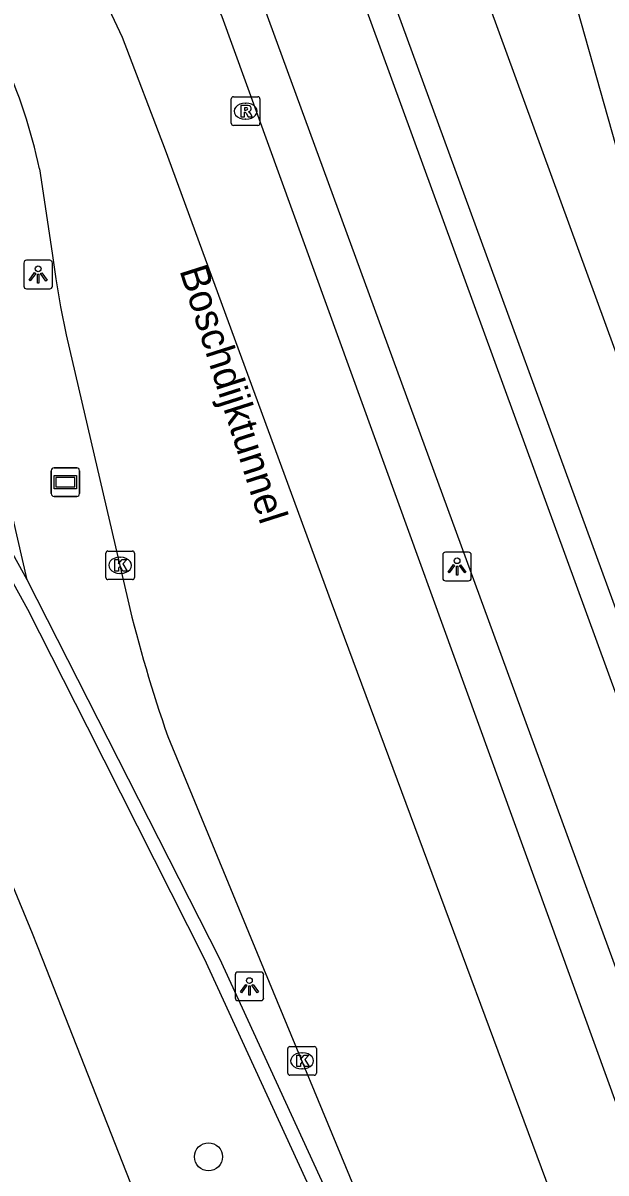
# Model space of a CAD drawing. Extents: x 160806 to 161707, y 383697 to 384148.
# Drawn here: x 161073.56 to 161093.93, y 383742.52 to 383782.67 of the extents above; entities that cross this region are included whole.
import ezdxf

# ---------------------------------------------------------------- set-up
doc = ezdxf.new("R2010")
doc.units = 0
for name, color, linetype in [('IMGEO_Boom', 7, 'Continuous'), ('IMGEO_Fietspad_open', 7, 'Continuous'), ('IMGEO_Kolk', 7, 'Continuous'), ('IMGEO_Lichtpunt', 7, 'Continuous'), ('IMGEO_Muur', 7, 'Continuous'), ('IMGEO_Openbare_ruimte_label', 7, 'Continuous'), ('IMGEO_OVBaan_gesloten', 7, 'Continuous'), ('IMGEO_Reclamebord', 7, 'Continuous'), ('IMGEO_Rijbaan_lokaal_gesloten', 7, 'Continuous'), ('IMGEO_Rioolput', 7, 'Continuous'), ('IMGEO_Voetpad_open', 7, 'Continuous')]:
    doc.layers.add(name, color=color, linetype=linetype)

msp = doc.modelspace()

# ---------------------------------------------------------------- linework, layer by layer
at = {"layer": 'IMGEO_Boom'}
msp.add_circle((161080.04, 383743.082), 0.489, dxfattribs=at)
at = {"layer": 'IMGEO_Fietspad_open'}
msp.add_lwpolyline([(161080.705, 383733.661), (161080.57, 383734.119), (161077.712, 383741.17), (161074.242, 383750), (161073.898, 383750.874), (161072.088, 383755.217), (161071.934, 383755.585)], dxfattribs=at)
at = {"layer": 'IMGEO_Kolk'}
for p, q in [((161076.453, 383763.307), (161076.453, 383764.159)), ((161076.528, 383764.233), (161077.38, 383764.233)), ((161076.941, 383764.013), (161076.966, 383764.013)), ((161077.454, 383764.159), (161077.454, 383763.307)), ((161077.38, 383763.233), (161076.528, 383763.233)), ((161076.964, 383763.453), (161076.939, 383763.453)), ((161082.809, 383746.006), (161082.809, 383746.858)), ((161082.884, 383746.932), (161083.736, 383746.932)), ((161083.297, 383746.712), (161083.322, 383746.712)), ((161083.81, 383746.858), (161083.81, 383746.006)), ((161083.736, 383745.932), (161082.884, 383745.932)), ((161083.32, 383746.152), (161083.295, 383746.152))]:
    msp.add_line(p, q, dxfattribs=at)
for points in [[(161076.453, 383763.307), (161076.453, 383764.159)], [(161076.528, 383764.233), (161077.38, 383764.233)], [(161076.774, 383763.933), (161076.897, 383763.933), (161076.897, 383763.782), (161077.027, 383763.933), (161077.191, 383763.933), (161077.045, 383763.782), (161077.198, 383763.533), (161077.046, 383763.533), (161076.961, 383763.697), (161076.897, 383763.63), (161076.897, 383763.533), (161076.774, 383763.533), (161076.774, 383763.933)], [(161077.454, 383764.159), (161077.454, 383763.307)], [(161077.38, 383763.233), (161076.528, 383763.233)], [(161082.809, 383746.006), (161082.809, 383746.858)], [(161082.884, 383746.932), (161083.736, 383746.932)], [(161083.81, 383746.858), (161083.81, 383746.006)], [(161083.13, 383746.632), (161083.253, 383746.632), (161083.253, 383746.481), (161083.383, 383746.632), (161083.547, 383746.632), (161083.401, 383746.481), (161083.554, 383746.232), (161083.402, 383746.232), (161083.317, 383746.396), (161083.253, 383746.329), (161083.253, 383746.232), (161083.13, 383746.232), (161083.13, 383746.632)], [(161083.736, 383745.932), (161082.884, 383745.932)]]:
    msp.add_lwpolyline(points, dxfattribs=at)
for centre, start, end in [((161076.53, 383764.157), 91.552, 178.448), ((161076.53, 383764.157), 91.552, 178.448), ((161077.378, 383764.157), 1.552, 88.448), ((161077.378, 383764.157), 1.552, 88.448), ((161076.53, 383763.309), 181.552, 268.448), ((161076.53, 383763.309), 181.552, 268.448), ((161077.378, 383763.309), 271.552, 358.448), ((161077.378, 383763.309), 271.552, 358.448), ((161082.886, 383746.856), 91.552, 178.448), ((161082.886, 383746.856), 91.552, 178.448), ((161083.734, 383746.856), 1.552, 88.448), ((161083.734, 383746.856), 1.552, 88.448), ((161082.886, 383746.008), 181.552, 268.448), ((161082.886, 383746.008), 181.552, 268.448), ((161083.734, 383746.008), 271.552, 358.448), ((161083.734, 383746.008), 271.552, 358.448)]:
    msp.add_arc(centre, 0.0765, start, end, dxfattribs=at)
for centre, major_axis, ratio, start_param, end_param in [((161076.94, 383763.733), (-0.387, 0.002), 0.722429, 4.712389, 7.853982), ((161076.965, 383763.733), (-0.39, 0.002), 0.717154, 1.570796, 4.712389), ((161083.296, 383746.432), (-0.387, 0.002), 0.722429, 4.712389, 7.853982), ((161083.321, 383746.432), (-0.39, 0.002), 0.717154, 1.570796, 4.712389)]:
    msp.add_ellipse(centre, major_axis=major_axis, ratio=ratio, start_param=start_param, end_param=end_param, dxfattribs=at)
at = {"layer": 'IMGEO_Lichtpunt'}
for p, q in [((161074.493, 383774.382), (161073.685, 383774.382)), ((161074.493, 383774.382), (161073.685, 383774.382)), ((161073.591, 383774.287), (161073.591, 383773.48)), ((161073.591, 383774.287), (161073.591, 383773.48)), ((161074.587, 383773.48), (161074.587, 383774.287)), ((161074.587, 383773.48), (161074.587, 383774.287)), ((161073.685, 383773.386), (161074.493, 383773.386)), ((161073.685, 383773.386), (161074.493, 383773.386)), ((161088.224, 383764.093), (161088.224, 383763.286)), ((161088.224, 383764.093), (161088.224, 383763.286)), ((161089.126, 383764.188), (161088.318, 383764.188)), ((161089.126, 383764.188), (161088.318, 383764.188)), ((161089.22, 383763.286), (161089.22, 383764.093)), ((161089.22, 383763.286), (161089.22, 383764.093)), ((161088.318, 383763.192), (161089.126, 383763.192)), ((161088.318, 383763.192), (161089.126, 383763.192)), ((161081.873, 383749.531), (161081.065, 383749.531)), ((161081.873, 383749.531), (161081.065, 383749.531)), ((161080.971, 383749.436), (161080.971, 383748.629)), ((161080.971, 383749.436), (161080.971, 383748.629)), ((161081.967, 383748.629), (161081.967, 383749.436)), ((161081.967, 383748.629), (161081.967, 383749.436)), ((161081.065, 383748.535), (161081.873, 383748.535)), ((161081.065, 383748.535), (161081.873, 383748.535))]:
    msp.add_line(p, q, dxfattribs=at)
for points in [[(161073.965, 383773.951), (161074.004, 383773.923), (161073.816, 383773.661), (161073.778, 383773.688), (161073.965, 383773.951)], [(161074.067, 383773.903), (161074.114, 383773.903), (161074.114, 383773.581), (161074.067, 383773.581), (161074.067, 383773.903)], [(161074.177, 383773.923), (161074.215, 383773.95), (161074.402, 383773.688), (161074.363, 383773.66), (161074.177, 383773.923)], [(161088.598, 383763.757), (161088.637, 383763.729), (161088.449, 383763.467), (161088.411, 383763.494), (161088.598, 383763.757)], [(161088.7, 383763.709), (161088.747, 383763.709), (161088.747, 383763.387), (161088.7, 383763.387), (161088.7, 383763.709)], [(161088.81, 383763.729), (161088.848, 383763.756), (161089.035, 383763.494), (161088.996, 383763.466), (161088.81, 383763.729)], [(161081.345, 383749.1), (161081.384, 383749.072), (161081.196, 383748.81), (161081.158, 383748.837), (161081.345, 383749.1)], [(161081.557, 383749.072), (161081.595, 383749.099), (161081.782, 383748.837), (161081.743, 383748.809), (161081.557, 383749.072)], [(161081.447, 383749.052), (161081.494, 383749.052), (161081.494, 383748.73), (161081.447, 383748.73), (161081.447, 383749.052)]]:
    msp.add_lwpolyline(points, dxfattribs=at)
for centre in [(161074.09, 383774.085), (161088.723, 383763.891), (161081.47, 383749.234)]:
    msp.add_circle(centre, 0.0994, dxfattribs=at)
for centre, start, end in [((161073.685, 383774.287), 90, 180), ((161073.685, 383774.287), 90, 180), ((161074.493, 383774.287), 0, 90), ((161074.493, 383774.287), 0, 90), ((161073.685, 383773.48), 180, 270), ((161073.685, 383773.48), 180, 270), ((161074.493, 383773.48), 270, 0), ((161074.493, 383773.48), 270, 360), ((161088.318, 383764.093), 90, 180), ((161088.318, 383764.093), 90, 180), ((161089.126, 383764.093), 0, 90), ((161089.126, 383764.093), 0, 90), ((161088.318, 383763.286), 180, 270), ((161088.318, 383763.286), 180, 270), ((161089.126, 383763.286), 270, 0), ((161089.126, 383763.286), 270, 360), ((161081.065, 383749.436), 90, 180), ((161081.065, 383749.436), 90, 180), ((161081.873, 383749.436), 0, 90), ((161081.873, 383749.436), 0, 90), ((161081.065, 383748.629), 180, 270), ((161081.065, 383748.629), 180, 270), ((161081.873, 383748.629), 270, 0), ((161081.873, 383748.629), 270, 360)]:
    msp.add_arc(centre, 0.0946, start, end, dxfattribs=at)
at = {"layer": 'IMGEO_Muur'}
for points in [[(161073.707, 383763.229), (161070.603, 383768.827), (161066.874, 383775.139), (161061.104, 383784.003)], [(161084.716, 383740.669), (161084.276, 383740.472), (161079.903, 383750), (161075.811, 383758.082), (161073.73, 383762.192), (161070.184, 383768.589), (161066.462, 383774.885), (161064.925, 383777.254)], [(161084.716, 383740.669), (161080.436, 383750), (161073.707, 383763.229)]]:
    msp.add_lwpolyline(points, dxfattribs=at)
at = {"layer": 'IMGEO_OVBaan_gesloten'}
for points in [[(161102.235, 383750), (161101.051, 383753.951), (161098.374, 383763.844), (161092.283, 383785.463), (161090.16, 383792.842)], [(161103.041, 383747.674), (161101.686, 383750.837), (161094.204, 383771.373), (161086.746, 383791.803)], [(161083.782, 383790.902), (161086.058, 383784.64), (161097.094, 383754.459)], [(161096.146, 383754.129), (161082.829, 383790.612)], [(161095.134, 383747.328), (161080.062, 383788.476)]]:
    msp.add_lwpolyline(points, dxfattribs=at)
at = {"layer": 'IMGEO_Reclamebord'}
for p, q in [((161074.646, 383767.138), (161075.436, 383767.138)), ((161075.436, 383767.138), (161074.646, 383767.138)), ((161074.546, 383766.238), (161074.546, 383767.038)), ((161074.546, 383767.038), (161074.546, 383766.238)), ((161075.536, 383767.038), (161075.536, 383766.238)), ((161075.536, 383766.238), (161075.536, 383767.038)), ((161075.436, 383766.138), (161074.646, 383766.138)), ((161074.646, 383766.138), (161075.436, 383766.138))]:
    msp.add_line(p, q, dxfattribs=at)
for points in [[(161074.647, 383766.87), (161075.435, 383766.87), (161075.435, 383766.406), (161074.647, 383766.406), (161074.647, 383766.87)], [(161074.712, 383766.805), (161074.712, 383766.471), (161075.37, 383766.471), (161075.37, 383766.805), (161074.712, 383766.805)]]:
    msp.add_lwpolyline(points, dxfattribs=at)
for centre, start, end in [((161074.646, 383767.038), 90, 180), ((161074.646, 383767.038), 90, 180), ((161075.436, 383767.038), 0, 90), ((161075.436, 383767.038), 360, 90), ((161074.646, 383766.238), 180, 270), ((161074.646, 383766.238), 180, 270), ((161075.436, 383766.238), 270, 0), ((161075.436, 383766.238), 270, 0)]:
    msp.add_arc(centre, 0.1, start, end, dxfattribs=at)
at = {"layer": 'IMGEO_Rijbaan_lokaal_gesloten'}
for points in [[(161094.759, 383743.637), (161080.521, 383782.879), (161078.277, 383787.537), (161077.524, 383788.998)], [(161074.06, 383787.945), (161075.725, 383784.96), (161077.022, 383782.168), (161078.529, 383778.234), (161084.322, 383762.444), (161094.418, 383735.279), (161098.056, 383725.946), (161105.565, 383706.821)], [(161074.138, 383777.58), (161074.579, 383774.627), (161074.704, 383773.732), (161074.871, 383772.76), (161075.07, 383771.78), (161077.219, 383762.531)], [(161078.621, 383757.758), (161081.827, 383750), (161085.301, 383741.593)]]:
    msp.add_lwpolyline(points, dxfattribs=at)
for centre, radius, start, end in [((161054.965, 383773.421), 19.619, 12.2378, 24.1977), ((161124.66, 383773.874), 48.778, 193.4464, 199.2923)]:
    msp.add_arc(centre, radius, start, end, dxfattribs=at)
at = {"layer": 'IMGEO_Rioolput'}
for p, q in [((161080.837, 383779.166), (161080.837, 383780.018)), ((161080.912, 383780.092), (161081.764, 383780.092)), ((161081.838, 383780.018), (161081.838, 383779.166)), ((161081.325, 383779.872), (161081.35, 383779.872)), ((161081.348, 383779.312), (161081.323, 383779.312)), ((161081.764, 383779.092), (161080.912, 383779.092))]:
    msp.add_line(p, q, dxfattribs=at)
for points in [[(161080.837, 383779.166), (161080.837, 383780.018)], [(161080.912, 383780.092), (161081.764, 383780.092)], [(161081.838, 383780.018), (161081.838, 383779.166)], [(161081.426, 383779.79), (161081.174, 383779.792), (161081.174, 383779.392)], [(161081.352, 383779.711), (161081.298, 383779.711), (161081.298, 383779.63)], [(161081.298, 383779.63), (161081.35, 383779.63)], [(161081.174, 383779.392), (161081.298, 383779.392), (161081.298, 383779.554), (161081.309, 383779.554)], [(161081.356, 383779.525), (161081.427, 383779.392), (161081.567, 383779.392), (161081.502, 383779.518)], [(161081.764, 383779.092), (161080.912, 383779.092)]]:
    msp.add_lwpolyline(points, dxfattribs=at)
for centre, radius, start, end in [((161080.914, 383780.016), 0.0765, 91.552, 178.448), ((161080.914, 383780.016), 0.0765, 91.552, 178.448), ((161081.762, 383780.016), 0.0765, 1.552, 88.448), ((161081.762, 383780.016), 0.0765, 1.552, 88.448), ((161081.334, 383779.819), 0.19, 274.7715, 282.9687), ((161081.358, 383779.615), 0.0964, 77.0061, 93.1865), ((161081.372, 383779.672), 0.0378, 276.6634, 79.6772), ((161081.425, 383779.68), 0.109, 350.3612, 89.416), ((161081.423, 383779.68), 0.112, 277.5842, 350.9817), ((161081.308, 383779.501), 0.0533, 26.0293, 88.6989), ((161081.407, 383779.465), 0.108, 29.5134, 73.7905), ((161080.914, 383779.168), 0.0765, 181.552, 268.448), ((161080.914, 383779.168), 0.0765, 181.552, 268.448), ((161081.762, 383779.168), 0.0765, 271.552, 358.448), ((161081.762, 383779.168), 0.0765, 271.552, 358.448)]:
    msp.add_arc(centre, radius, start, end, dxfattribs=at)
for centre, major_axis, ratio, start_param, end_param in [((161081.324, 383779.592), (-0.387, 0.002), 0.722429, 4.712389, 7.853982), ((161081.349, 383779.592), (-0.39, 0.002), 0.717154, 1.570796, 4.712389)]:
    msp.add_ellipse(centre, major_axis=major_axis, ratio=ratio, start_param=start_param, end_param=end_param, dxfattribs=at)
at = {"layer": 'IMGEO_Voetpad_open'}
msp.add_lwpolyline([(161073.707, 383763.229), (161072.059, 383770.328)], dxfattribs=at)

# ---------------------------------------------------------------- texts
at = {"layer": 'IMGEO_Openbare_ruimte_label'}
msp.add_text('Boschdijktunnel', height=1, rotation=287.6923, dxfattribs=at).set_placement((161079.018, 383774.033))

doc.saveas('drawing.dxf')
